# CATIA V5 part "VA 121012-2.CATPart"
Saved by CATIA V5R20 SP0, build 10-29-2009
Part number: VA 121012-2
Revision: ANY
Definition: UNKNOWN
Nomenclature: VA 121012-2
Source: Unknown
Bounding box of the stored display mesh (mm): x -5.85 to 5.85, y 0 to 12, z -6 to 6
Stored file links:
  C:\Users\Utente\Desktop\IO LAVORO\3D X SITO CF\CUMSA\3D files VA\VA 121012\VA 121012-2.CATPart
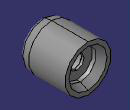
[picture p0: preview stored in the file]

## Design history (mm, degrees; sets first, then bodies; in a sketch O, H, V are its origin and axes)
Body1 "Redondeo1" (main body)
  Solid1: solid without history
